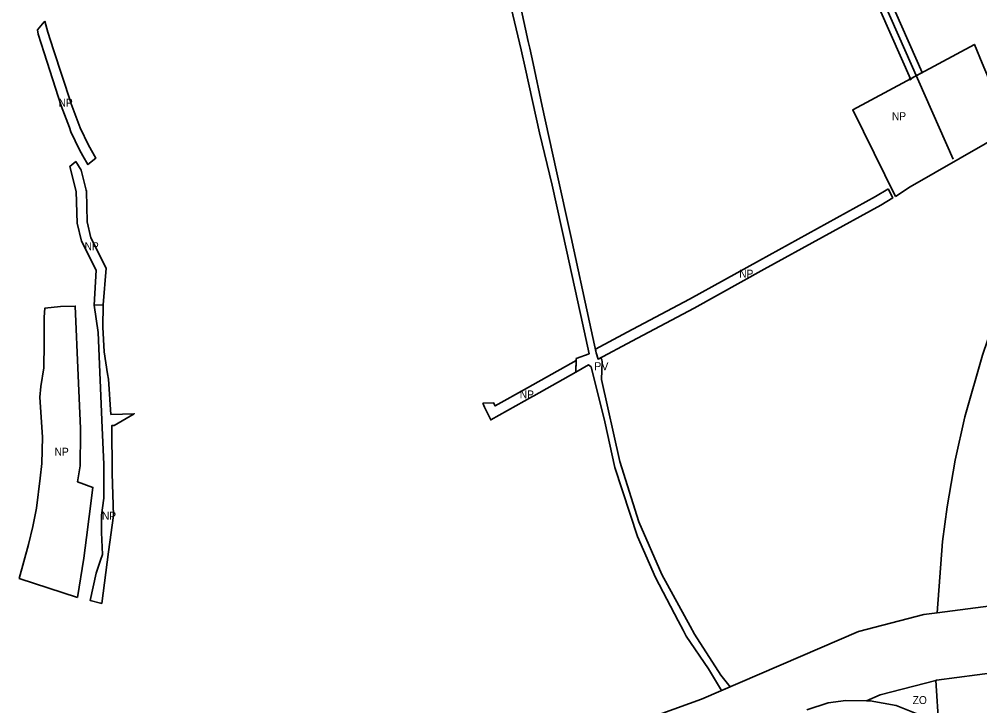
# Model space of a CAD drawing. Extents: x -650276 to -642489, y -1074311 to -1066658.
# Drawn here: x -649415 to -647975, y -1069108 to -1068079 of the extents above; entities that cross this region are included whole.
import ezdxf

# ---------------------------------------------------------------- set-up
doc = ezdxf.new("R2010")
doc.units = 0
doc.header["$LTSCALE"] = 4.8
doc.header["$PDMODE"] = 32
doc.header["$PDSIZE"] = 2.4
for name, color, linetype, lineweight in [('15', 7, 'Continuous', 35), ('24', 7, 'Continuous', 35), ('25', 7, 'Continuous', 35), ('42', 7, 'Continuous', 35), ('48', 7, 'Continuous', 35), ('54', 7, 'Continuous', 35)]:
    doc.layers.add(name, color=color, linetype=linetype, lineweight=lineweight)
doc.layers.add('62', color=7, linetype='Continuous')
doc.layers.add('63', color=7, linetype='Continuous')

msp = doc.modelspace()

# ---------------------------------------------------------------- linework, layer by layer
at = {"layer": '15'}
for points in [[(-648668.92, -1068032.96), (-648651.89, -1068111.95), (-648649.74, -1068121.95), (-648644.73, -1068145.27), (-648630.99, -1068209.19), (-648610.14, -1068304.32), (-648587.39, -1068405.82), (-648559.91, -1068532.62), (-648549.84, -1068578.65), (-648547.25, -1068588.14), (-648542.93, -1068586.13), (-648541.74, -1068589.27)], [(-648349.419, -1069079.223), (-648362.06, -1069084.664), (-648381.44, -1069052.48), (-648415.29, -1069003.16), (-648419.78, -1068994.25), (-648427.21, -1068980.13), (-648461.22, -1068915.44), (-648488.09, -1068854.16), (-648521.92, -1068750.34), (-648537.29, -1068681.95), (-648557.4, -1068599.9), (-648559.44, -1068598.37), (-648561.49, -1068596.84), (-648580.66, -1068607.64), (-648579.97, -1068587.39), (-648560.79, -1068580.12), (-648572.95, -1068522.97), (-648573.96, -1068518.34), (-648594.38, -1068425.02), (-648615.87, -1068327.3), (-648634.84, -1068248.76), (-648655.88, -1068153.63), (-648662.71, -1068124.76), (-648677.61, -1068061.74)], [(-648541.74, -1068589.27), (-648541.25, -1068592.3), (-648541.89, -1068618.64), (-648514.35, -1068741.53), (-648486.25, -1068831.83), (-648451.76, -1068910.91), (-648409.15, -1068988.44), (-648402.76, -1069000.2), (-648363.11, -1069061.72), (-648349.419, -1069079.223)]]:
    msp.add_lwpolyline(points, dxfattribs=at)
at = {"layer": '24'}
for points in [[(-647864.531, -1068951.823), (-647895.901, -1068953.392), (-647958.168, -1068957.73), (-648038.596, -1068968.281), (-648038.759, -1068968.54)], [(-648038.759, -1068968.54), (-648038.746, -1068968.301), (-648058.764, -1068970.927), (-648156.739, -1068996.273), (-648392.002, -1069097.554), (-648451.865, -1069119.456)], [(-648040.705, -1069069.547), (-648039.666, -1069069.279), (-647948.18, -1069057.276), (-647886.615, -1069053.052), (-647856.541, -1069051.548), (-647848.615, -1069051.679), (-647842.888, -1069051.774), (-647814.401, -1069052.246)], [(-648234.22, -1069113.6), (-648202.46, -1069103.3), (-648175.65, -1069099.64), (-648144.866, -1069099.987), (-648124.327, -1069091.181), (-648040.705, -1069069.547)]]:
    msp.add_lwpolyline(points, dxfattribs=at)
at = {"layer": '25'}
msp.add_line((-648038.596, -1068968.281), (-647958.168, -1068957.73), dxfattribs=at)
for points in [[(-647801.797, -1068219.34), (-647843.6, -1068292.629), (-647868.214, -1068337.803), (-647914.339, -1068432.512), (-647946.187, -1068510.254), (-647971.074, -1068581.98), (-647997.27, -1068674.747), (-648011.775, -1068739.718), (-648023.914, -1068809.332), (-648030.73, -1068861.213), (-648038.596, -1068968.281)], [(-647948.18, -1069057.276), (-648039.666, -1069069.279), (-648040.705, -1069069.548), (-648036.291, -1069139.458)]]:
    msp.add_lwpolyline(points, dxfattribs=at)
at = {"layer": '42'}
msp.add_lwpolyline([(-648100.37, -1069107.1), (-648065.16, -1069121.12), (-648048.06, -1069130.81), (-648036.291, -1069139.458), (-648040.705, -1069069.547), (-648124.327, -1069091.181), (-648144.867, -1069099.987), (-648139.27, -1069100.05), (-648100.37, -1069107.1)], close=True, dxfattribs=at)
at = {"layer": '48'}
for points in [[(-648238.748, -1067756.759), (-648256.499, -1067766.091), (-648079.002, -1068168.139)], [(-648079.002, -1068168.139), (-648061.329, -1068158.649), (-648232.676, -1067770.513)], [(-649302.681, -1068507.363), (-649296.55, -1068548.09), (-649290.93, -1068690.93), (-649287.98, -1068745.74), (-649288.19, -1068786.39), (-649288.24, -1068796.6), (-649291.64, -1068821.88), (-649291.87, -1068848.02), (-649290.28, -1068880.82), (-649293.33, -1068889.65), (-649299.91, -1068908.66), (-649308.65, -1068950), (-649293.04, -1068953.81), (-649291.32, -1068954.23), (-649281.01, -1068876.69), (-649273.66, -1068822.58), (-649275.96, -1068759.73), (-649276.43, -1068688.29), (-649276.474, -1068687.673), (-649272.755, -1068687.618)], [(-649277.655, -1068670.983), (-649281.4, -1068618.05), (-649282.97, -1068610.04), (-649287.71, -1068577.14), (-649289.74, -1068540.2), (-649289.24, -1068506.8), (-649302.681, -1068507.363)], [(-649272.755, -1068687.618), (-649272.69, -1068687.58), (-649242.507, -1068669.925), (-649277.655, -1068670.983)]]:
    msp.add_lwpolyline(points, dxfattribs=at)
for points in [[(-649376.467, -1068081.552), (-649377.77, -1068082.44), (-649387.46, -1068094.51), (-649386.74, -1068101.31), (-649377.81, -1068129), (-649352.11, -1068208.65), (-649339.94, -1068241.13), (-649337.52, -1068247.59), (-649324.66, -1068274.3), (-649319.551, -1068283.382), (-649312.087, -1068296.653), (-649300.305, -1068287.002), (-649311.352, -1068267.362), (-649323.711, -1068241.693), (-649337.178, -1068205.751), (-649337.942, -1068203.713), (-649363.534, -1068124.395), (-649371.987, -1068098.185)], [(-648101.42, -1068344.28), (-648079.33, -1068330.03), (-647929.45, -1068244.16), (-647971.35, -1068144.48), (-647982.969, -1068116.575), (-648165.28, -1068214.465)], [(-649330.038, -1068291.976), (-649339.046, -1068299.359), (-649329.644, -1068336.779), (-649328.386, -1068384.468), (-649321.727, -1068411.472), (-649299.894, -1068454.728), (-649302.681, -1068507.363), (-649289.24, -1068506.8), (-649284.59, -1068451.76), (-649307.57, -1068406.23), (-649313.42, -1068382.51), (-649314.27, -1068336.41), (-649314.693, -1068334.727), (-649322.18, -1068304.93)], [(-648112.198, -1068333.037), (-648112.92, -1068333.424), (-648131.034, -1068344.388), (-648305.242, -1068440.3), (-648410.111, -1068498.408), (-648503.768, -1068547.914), (-648551.041, -1068573.16), (-648549.84, -1068578.65), (-648547.25, -1068588.14), (-648496.73, -1068561.16), (-648402.97, -1068511.6), (-648297.99, -1068453.43), (-648123.53, -1068357.38), (-648105.49, -1068346.46)], [(-649327.679, -1068945.222), (-649318.13, -1068886.42), (-649314.07, -1068855.33), (-649310.01, -1068824.2), (-649304.66, -1068780.33), (-649327.8, -1068771.82), (-649323.68, -1068748.06), (-649323.1, -1068699.28), (-649323.02, -1068692.1), (-649326.53, -1068612.89), (-649331.151, -1068508.557), (-649353.17, -1068509.48), (-649376.77, -1068511.96), (-649377.52, -1068525.1), (-649377.56, -1068564.89), (-649378.08, -1068601.24), (-649382.46, -1068629.34), (-649384.31, -1068644.92), (-649379.97, -1068704.98), (-649381.06, -1068744.69), (-649383.78, -1068766.6), (-649389.34, -1068811.43), (-649394.48, -1068838.89), (-649401.31, -1068865.78), (-649415.09, -1068917.1)], [(-648720.238, -1068654.205), (-648717.32, -1068660.24), (-648708.14, -1068679.23), (-648645.69, -1068644.27), (-648643.654, -1068643.123), (-648580.66, -1068607.64), (-648580.062, -1068590.087), (-648588.022, -1068594.571), (-648653.034, -1068631.191), (-648701.568, -1068658.36), (-648703.816, -1068653.711)]]:
    msp.add_lwpolyline(points, close=True, dxfattribs=at)
msp.add_point((-648079.002, -1068168.139), dxfattribs=at)
at = {"layer": '54'}
msp.add_lwpolyline([(-648383.36, -1067413.938), (-648264.607, -1067722.965), (-648014.937, -1068288.491)], dxfattribs=at)

# ---------------------------------------------------------------- texts
at = {"layer": '62', "width": 0.95}
for s, p in [('NP', (-649355.985, -1068209.967)), ('NP', (-648106.583, -1068230.041)), ('NP', (-649316.985, -1068424.967)), ('NP', (-648335.583, -1068466.041)), ('NP', (-648664.583, -1068647.041)), ('NP', (-649361.985, -1068732.967)), ('NP', (-649290.985, -1068828.967)), ('ZO', (-648075.473, -1069105.058))]:
    msp.add_text(s, height=12, dxfattribs=at).set_placement(p)
at = {"layer": '63'}
msp.add_text('PV', height=12, dxfattribs=at).set_placement((-648552.984, -1068604.692))

doc.saveas('drawing.dxf')
